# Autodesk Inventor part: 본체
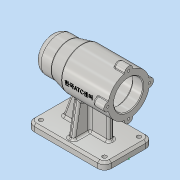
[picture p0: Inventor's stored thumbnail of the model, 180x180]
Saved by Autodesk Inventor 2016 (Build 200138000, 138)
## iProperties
Created: 2019-07
Part Number: 본체
Material: 알루미늄 6061
Document SubType Name: Modeling
Designer: Administrator
Density: 2.7 g/cm^3
Appearance: 알루미늄 - 평지
Mass: 644.388 g
Surface Area: 654.094 cm^2
Volume: 238.662 cm^3
Author: Administrator
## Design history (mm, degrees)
sketch "스케치1"
  geometry: L1 (-56, -35)-(56, -35); L2 (56, -35)-(56, 35); L3 (56, 35)-(-56, 35); L4 (-56, 35)-(-56, -35); L5 (-56, -35)-(56, 35); L6 (56, -35)-(-56, 35); 1 further point
  constraints: 12 end point, 2 midpoint, 2 parallel, 1 horizontal, 1 perpendicular
  dimensions: "d0" = 112 distance of L3.end L2.end; "d1" = 70 distance of L2.end L1.end
extrude "돌출1" new body sketch "스케치1" distance "d2" = 10; taper "d3" = 0 deg
sketch "스케치2"
  geometry: L1 (83.671, 80)-(-69.466, 80); L2 (-56, 80)-(-56, 110); L3 (-56, 110)-(11, 110); L4 (11, 110)-(31, 105); L5 (31, 105)-(56, 105); L6 (56, 105)-(56, 80); L7 (-56, 80)-(56, 80); 1 further point
  constraints: 14 end point, 2 perpendicular, 2 point on line, 1 collinear, 1 horizontal, 1 parallel, 1 vertical
  dimensions: "d5" = 60 diameter of L3 L1; "d6" = 50 diameter of L5 L1; "d9" = 112 distance between parallel lines of L2 L6; "d10" = 25 distance of L4.end L5.end; "d11" = 45 distance from line of L6 L3.end
revolve "회전1" sketch "스케치2" stored, may be unused: angle "d12" = 90 deg
sketch "스케치3"
  geometry: L1 (71.199, 80)-(-68.081, 80); L2 (-56, 50)-(11, 50) reference; L3 (-56, 101)-(-41, 101); L4 (-41, 101)-(-41, 104); L5 (-41, 104)-(13, 104); L6 (13, 104)-(13, 101); L7 (13, 101)-(25, 101); L8 (25, 101)-(25, 97.5); L9 (25, 97.5)-(43, 97.5); L10 (43, 97.5)-(43, 96); L11 (43, 96)-(47, 96); L12 (47, 96)-(47, 90.5); L13 (47, 90.5)-(50, 90.5); L14 (50, 90.5)-(50, 80); L15 (-56, 101)-(-56, 80); L16 (-56, 80)-(50, 80); 1 further point
  constraints: 30 end point, 9 perpendicular, 3 horizontal, 3 point on line
  dimensions: "d13" = 60 diameter of L2 L1; "d14" = 42 diameter of L3 L1; "d15" = 48 diameter of L5 L1; "d16" = 35 diameter of L9 L1; "d17" = 32 diameter of L11 L1; "d18" = 21 diameter of L13 L1; "d20" = 54 distance between parallel lines of L6 L4; "d21" = 12 distance of L6.end L7.end; "d22" = 18 distance of L8.end L9.end; "d23" = 4 distance of L10.end L11.end; "d24" = 3 distance of L12.end L13.end
revolve "회전2" sketch "스케치3" stored, may be unused: angle "d25" = 90 deg
sketch "스케치4"
  geometry: L1 (36, 10)-(20.111, 53.656); L2 (-31, 10)-(-31, 53.656); L3 (56, 0)-(56, 10) reference; L4 (-31, 53.656)-(20.111, 53.656); L5 (-31, 10)-(36, 10); L6 (56, 10)-(-56, 10) reference; 1 further point
  constraints: 8 end point, 1 horizontal, 1 vertical
  dimensions: "d27" = 20 distance from line of L3 L1.start; "d35" = 110 deg angle of L6 L1
extrude "돌출2" join sketch "스케치4" stored distance "d29" = 8; taper "d30" = 0 deg
sketch "스케치5"
  geometry: L1 (35, 10)-(-35, 10) reference; L2 (-28, 10)-(-19.147, 60.208); L3 (-35, 0)-(-35, 10) reference; L4 (-28, 10)-(0, 10); L5 (-4, 10)-(4, 10) reference; L6 (0, 10)-(0, 52.462); A1 r 30 centre (0, 80) between (4, 50.268) and (-4, 50.268) reference; A2 r 27.538 centre (0, 80) between (-19.147, 60.208) and (0, 52.462); 1 further point
  constraints: 6 end point, 2 point on circle, 1 centre point, 1 coincident, 1 midpoint, 1 point on line
  dimensions: "d31" = 7 distance from line of L3 L2.start; "d32" = 100 deg angle of L2 L1
extrude "돌출3" join sketch "스케치5" stored distance "d33" = 8; taper "d34" = 0 deg
sketch "스케치6"
  geometry: C1 r 6 at (-30, 0); 1 further point
  constraints: 1 centre point
  dimensions: "d36" = 6 radius of C1
extrude "돌출4" join sketch "스케치6" distance "d37" = 16; taper "d38" = 0 deg
sketch "스케치7"
  geometry: 1 further point
sketch "스케치8"
  geometry: A1 r 6 centre (0, 0) between (0.6, 5.97) and (0.6, -5.97) reference; 2 further points
  constraints: 1 coincident
hole "구멍1" sketch "스케치8" at (0, 0) diameter "d39" = 3.242; stored, may be unused: countersink angle "d43" = 90 deg, drill point angle "d45" = 118 deg; dims "d40" = 8, "d41" = 4, "d42" = 2, "d44" = 11
fillet "모깎기1" dims "d49" = 10
sketch "스케치9"
  geometry: C1 r 3 at (-46, -25); C2 r 3 at (-46, 25); C3 r 3 at (46, 25); C4 r 3 at (46, -25); A1 r 10 centre (-46, 25) between (-46, 35) and (-56, 25) reference; A2 r 10 centre (46, 25) between (56, 25) and (46, 35) reference; A3 r 10 centre (46, -25) between (46, -35) and (56, -25) reference; A4 r 10 centre (-46, -25) between (-56, -25) and (-46, -35) reference; 1 further point
  constraints: 4 centre point, 4 coincident
  dimensions: "d50" = 6 diameter of C1; "d51" = 6 diameter of C2; "d52" = 6 diameter of C3; "d53" = 6 diameter of C4
extrude "돌출5" cut sketch "스케치9" stored distance "d54" = 0; taper "d55" = 0 deg
chamfer "모따기1" distance "d56" = 3; stored, may be unused: second distance "d57" = 2, angle "d58" = 45 deg
chamfer "모따기2" distance "d59" = 1; stored, may be unused: second distance "d60" = 2, angle "d61" = 45 deg
fillet "모깎기2" dims "d62" = 0.3
fillet "모깎기3" dims "d63" = 3
fillet "모깎기4" dims "d64" = 3
fillet "모깎기5" dims "d65" = 10
fillet "모깎기6" dims "d66" = 3
fillet "모깎기7" dims "d67" = 1
node "작업 평면1"
sketch "스케치10"
  geometry: L1 (33.5, -6.771)-(33.5, -29.226) reference; L2 (-78.5, -15)-(-78.5, 15) reference; L3 (33.5, -22)-(33.5, 22) reference; L4 (16.5, 30)-(-33.131, 30) reference; 2 further points
  constraints: 1 other
  dimensions: "d68" = 42 distance from line of L1 point (-8.5, 0); "d69" = 30 distance from line of L4 point (-8.5, 0)
feature "엠보싱1" sketch "스케치10" dims "d0" = 112, "d1" = 70, "d70" = 0.5, "d71" = 0
node "솔리드1"
mirror "대칭1"
pattern_circular "원형 패턴1" dims angle "d47" = 360 deg
